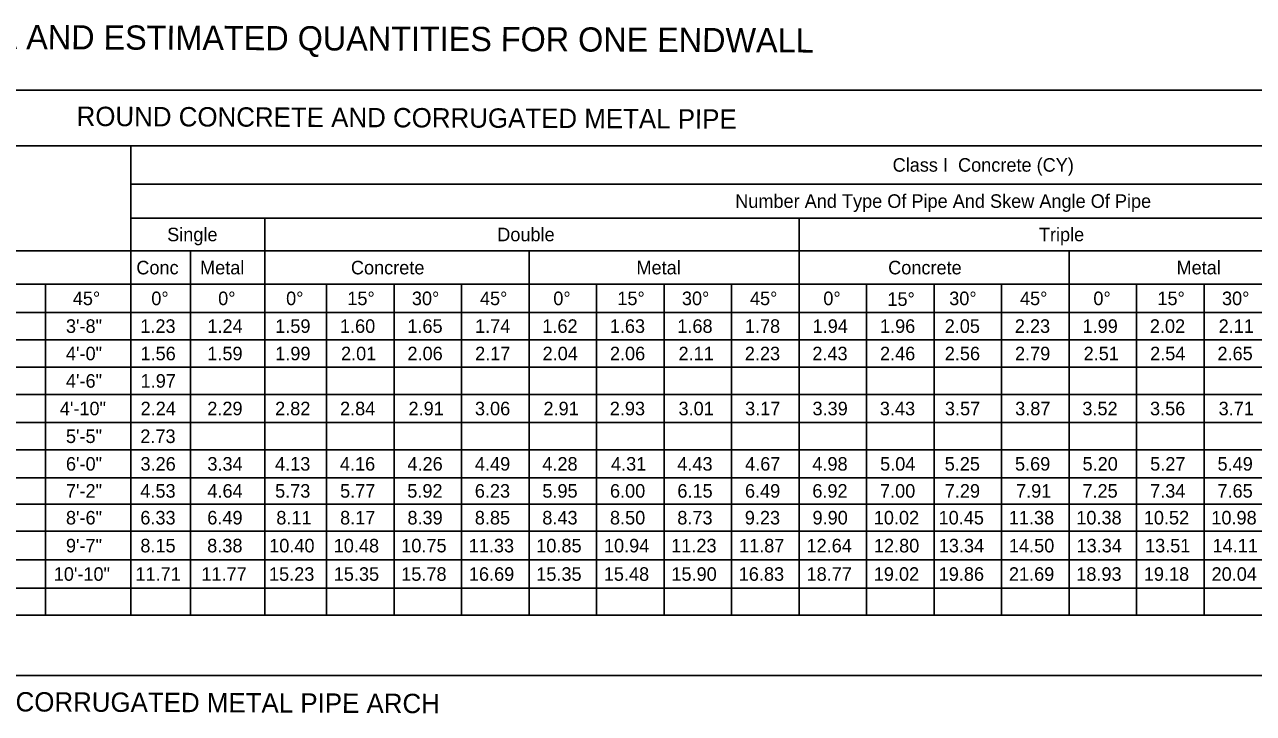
# Model space of a CAD drawing. Extents: x 10029 to 10796, y 10063 to 10519.
# Drawn here: x 10299.4 to 10616.8, y 10341.1 to 10518.9 of the extents above; entities that cross this region are included whole.
import ezdxf

# ---------------------------------------------------------------- set-up
doc = ezdxf.new("R2010")
doc.units = 0
doc.layers.add('Default', color=7, linetype='Continuous')
doc.layers.add('TextStructures', color=7, linetype='Continuous')

msp = doc.modelspace()

# ---------------------------------------------------------------- linework, layer by layer
at = {"layer": 'Default'}
for p, q in [((10028.97, 10502.01), (10795.89, 10502.01)), ((10028.97, 10487.65), (10795.89, 10487.65)), ((10326.86, 10366.47), (10326.86, 10487.65)), ((10326.86, 10477.72), (10783.03, 10477.72)), ((10326.86, 10468.97), (10783.03, 10468.97)), ((10361.4, 10366.47), (10361.4, 10468.97)), ((10499.44, 10366.47), (10499.44, 10468.97)), ((10042.36, 10460.49), (10783.03, 10460.49)), ((10342.27, 10366.47), (10342.27, 10460.49)), ((10429.69, 10366.47), (10429.69, 10460.49)), ((10569.19, 10366.47), (10569.19, 10460.49)), ((10244.78, 10451.88), (10783.03, 10451.88)), ((10304.74, 10366.47), (10304.74, 10451.88)), ((10377.37, 10366.47), (10377.37, 10451.88)), ((10394.81, 10366.47), (10394.81, 10451.88)), ((10412.25, 10366.47), (10412.25, 10451.88)), ((10447.13, 10366.47), (10447.13, 10451.88)), ((10464.57, 10366.47), (10464.57, 10451.88)), ((10482, 10366.47), (10482, 10451.88)), ((10516.88, 10366.47), (10516.88, 10451.88)), ((10534.32, 10366.47), (10534.32, 10451.88)), ((10551.76, 10366.47), (10551.76, 10451.88)), ((10586.63, 10366.47), (10586.63, 10451.88)), ((10604.07, 10366.47), (10604.07, 10451.88)), ((10028.97, 10444.58), (10795.89, 10444.58)), ((10028.97, 10437.55), (10795.89, 10437.55)), ((10028.97, 10430.43), (10795.89, 10430.43)), ((10028.97, 10423.41), (10795.89, 10423.41)), ((10028.97, 10416.18), (10795.89, 10416.18)), ((10028.97, 10409.08), (10795.89, 10409.08)), ((10028.97, 10401.92), (10795.89, 10401.92)), ((10028.97, 10395.12), (10795.89, 10395.12)), ((10028.97, 10388.08), (10795.89, 10388.08)), ((10028.97, 10380.7), (10795.89, 10380.7)), ((10028.97, 10373.4), (10795.89, 10373.4)), ((10028.97, 10366.47), (10795.89, 10366.47)), ((10039.72, 10350.86), (10681.45, 10350.86))]:
    msp.add_line(p, q, dxfattribs=at)

# ---------------------------------------------------------------- texts
at = {"layer": 'TextStructures'}
for s, height, rotation, p in [('DATA AND ESTIMATED QUANTITIES FOR ONE ENDWALL', 6.25, 359.7555, (10275.18, 10512.68)), ('ROUND CONCRETE AND CORRUGATED METAL PIPE', 5, 359.7555, (10312.81, 10492.75)), ('3\'-8"', 3.5, 0, (10310.06, 10439.32)), ('1.23', 3.5, 0, (10329.27, 10439.32)), ('1.24', 3.5, 0, (10346.6, 10439.32)), ('1.59', 3.5, 0, (10364.12, 10439.32)), ('1.60', 3.5, 0, (10380.84, 10439.32)), ('1.65', 3.5, 0, (10398.25, 10439.32)), ('1.74', 3.5, 0, (10415.74, 10439.32)), ('1.62', 3.5, 0, (10433.11, 10439.32)), ('1.63', 3.5, 0, (10450.54, 10439.32)), ('1.68', 3.5, 0, (10467.99, 10439.32)), ('1.78', 3.5, 0, (10485.43, 10439.32)), ('1.94', 3.5, 0, (10502.93, 10439.32)), ('1.96', 3.5, 0, (10520.34, 10439.32)), ('2.05', 3.5, 0, (10537.05, 10439.32)), ('2.23', 3.5, 0, (10555.17, 10439.32)), ('1.99', 3.5, 0, (10572.65, 10439.32)), ('2.02', 3.5, 0, (10590.05, 10439.32)), ('2.11', 3.5, 0, (10607.81, 10439.32)), ('4\'-0"', 3.5, 0, (10310.06, 10432.24)), ('1.56', 3.5, 0, (10329.31, 10432.24)), ('1.59', 3.5, 0, (10346.57, 10432.24)), ('1.99', 3.5, 0, (10364.12, 10432.24)), ('2.01', 3.5, 0, (10381.11, 10432.24)), ('2.06', 3.5, 0, (10398.27, 10432.24)), ('2.17', 3.5, 0, (10415.75, 10432.24)), ('2.04', 3.5, 0, (10433.18, 10432.24)), ('2.06', 3.5, 0, (10450.58, 10432.24)), ('2.11', 3.5, 0, (10468.3, 10432.24)), ('2.23', 3.5, 0, (10485.42, 10432.24)), ('2.43', 3.5, 0, (10502.86, 10432.24)), ('2.46', 3.5, 0, (10520.34, 10432.24)), ('2.56', 3.5, 0, (10537.07, 10432.24)), ('2.79', 3.5, 0, (10555.21, 10432.24)), ('2.51', 3.5, 0, (10572.93, 10432.24)), ('2.54', 3.5, 0, (10590.12, 10432.24)), ('2.65', 3.5, 0, (10607.51, 10432.24)), ('4\'-6"', 3.5, 0, (10310.06, 10425.17)), ('1.97', 3.5, 0, (10329.35, 10425.17)), ('4\'-10"', 3.5, 0, (10308.48, 10418.04)), ('2.24', 3.5, 0, (10329.34, 10418.04)), ('2.29', 3.5, 0, (10346.57, 10418.04)), ('2.82', 3.5, 0, (10364.09, 10418.04)), ('2.84', 3.5, 0, (10380.86, 10418.04)), ('2.91', 3.5, 0, (10398.55, 10418.04)), ('3.06', 3.5, 0, (10415.71, 10418.04)), ('2.91', 3.5, 0, (10433.42, 10418.04)), ('2.93', 3.5, 0, (10450.54, 10418.04)), ('3.01', 3.5, 0, (10468.3, 10418.04)), ('3.17', 3.5, 0, (10485.5, 10418.04)), ('3.39', 3.5, 0, (10502.9, 10418.04)), ('3.43', 3.5, 0, (10520.3, 10418.04)), ('3.57', 3.5, 0, (10537.11, 10418.04)), ('3.87', 3.5, 0, (10555.26, 10418.04)), ('3.52', 3.5, 0, (10572.61, 10418.04)), ('3.56', 3.5, 0, (10590.09, 10418.04)), ('3.71', 3.5, 0, (10607.81, 10418.04)), ('5\'-5"', 3.5, 0, (10310.06, 10410.88)), ('2.73', 3.5, 0, (10329.27, 10410.88)), ('6\'-0"', 3.5, 0, (10310.06, 10403.75)), ('3.26', 3.5, 0, (10329.31, 10403.75)), ('3.34', 3.5, 0, (10346.6, 10403.75)), ('4.13', 3.5, 0, (10364.08, 10403.75)), ('4.16', 3.5, 0, (10380.83, 10403.75)), ('4.26', 3.5, 0, (10398.27, 10403.75)), ('4.49', 3.5, 0, (10415.71, 10403.75)), ('4.28', 3.5, 0, (10433.12, 10403.75)), ('4.31', 3.5, 0, (10450.86, 10403.75)), ('4.43', 3.5, 0, (10467.98, 10403.75)), ('4.67', 3.5, 0, (10485.5, 10403.75)), ('4.98', 3.5, 0, (10502.87, 10403.75)), ('5.04', 3.5, 0, (10520.37, 10403.75)), ('5.25', 3.5, 0, (10537.05, 10403.75)), ('5.69', 3.5, 0, (10555.21, 10403.75)), ('5.20', 3.5, 0, (10572.66, 10403.75)), ('5.27', 3.5, 0, (10590.13, 10403.75)), ('5.49', 3.5, 0, (10607.53, 10403.75)), ('7\'-2"', 3.5, 0, (10310.06, 10396.77)), ('4.53', 3.5, 0, (10329.27, 10396.77)), ('4.64', 3.5, 0, (10346.6, 10396.77)), ('5.73', 3.5, 0, (10364.08, 10396.77)), ('5.77', 3.5, 0, (10380.87, 10396.77)), ('5.92', 3.5, 0, (10398.23, 10396.77)), ('6.23', 3.5, 0, (10415.67, 10396.77)), ('5.95', 3.5, 0, (10433.12, 10396.77)), ('6.00', 3.5, 0, (10450.59, 10396.77)), ('6.15', 3.5, 0, (10468, 10396.77)), ('6.49', 3.5, 0, (10485.46, 10396.77)), ('6.92', 3.5, 0, (10502.86, 10396.77)), ('7.00', 3.5, 0, (10520.34, 10396.77)), ('7.29', 3.5, 0, (10537.07, 10396.77)), ('7.91', 3.5, 0, (10555.49, 10396.77)), ('7.25', 3.5, 0, (10572.63, 10396.77)), ('7.34', 3.5, 0, (10590.12, 10396.77)), ('7.65', 3.5, 0, (10607.51, 10396.77)), ('8\'-6"', 3.5, 0, (10310.06, 10389.85)), ('6.33', 3.5, 0, (10329.27, 10389.85)), ('6.49', 3.5, 0, (10346.57, 10389.85)), ('8.11', 3.5, 0, (10364.4, 10389.85)), ('8.17', 3.5, 0, (10380.87, 10389.85)), ('8.39', 3.5, 0, (10398.27, 10389.85)), ('8.85', 3.5, 0, (10415.68, 10389.85)), ('8.50', 3.5, 0, (10450.59, 10389.85)), ('8.73', 3.5, 0, (10467.98, 10389.85)), ('9.23', 3.5, 0, (10485.42, 10389.85)), ('9.90', 3.5, 0, (10502.91, 10389.85)), ('10.02', 3.5, 0, (10518.73, 10389.85)), ('10.45', 3.5, 0, (10535.48, 10389.85)), ('11.38', 3.5, 0, (10553.61, 10389.85)), ('10.38', 3.5, 0, (10571.05, 10389.85)), ('10.52', 3.5, 0, (10588.48, 10389.85)), ('10.98', 3.5, 0, (10605.93, 10389.85)), ('9\'-7"', 3.5, 0, (10310.06, 10382.64)), ('8.15', 3.5, 0, (10329.28, 10382.64)), ('8.38', 3.5, 0, (10346.55, 10382.64)), ('10.40', 3.5, 0, (10362.56, 10382.64)), ('10.48', 3.5, 0, (10379.23, 10382.64)), ('10.75', 3.5, 0, (10396.67, 10382.64)), ('11.33', 3.5, 0, (10414.1, 10382.64)), ('10.85', 3.5, 0, (10431.55, 10382.64)), ('10.94', 3.5, 0, (10449.04, 10382.64)), ('11.23', 3.5, 0, (10466.41, 10382.64)), ('11.87', 3.5, 0, (10483.93, 10382.64)), ('12.64', 3.5, 0, (10501.36, 10382.64)), ('12.80', 3.5, 0, (10518.77, 10382.64)), ('13.34', 3.5, 0, (10535.53, 10382.64)), ('14.50', 3.5, 0, (10553.65, 10382.64)), ('13.34', 3.5, 0, (10571.11, 10382.64)), ('13.51', 3.5, 0, (10588.8, 10382.64)), ('14.11', 3.5, 0, (10606.23, 10382.64)), ('10\'-10"', 3.5, 0, (10306.91, 10375.3)), ('11.71', 3.5, 0, (10328.01, 10375.3)), ('11.77', 3.5, 0, (10345.04, 10375.3)), ('15.23', 3.5, 0, (10362.51, 10375.3)), ('15.35', 3.5, 0, (10379.24, 10375.3)), ('15.78', 3.5, 0, (10396.67, 10375.3)), ('18.77', 3.5, 0, (10501.37, 10375.3)), ('19.02', 3.5, 0, (10518.73, 10375.3)), ('19.86', 3.5, 0, (10535.5, 10375.3)), ('21.69', 3.5, 0, (10553.64, 10375.3)), ('CORRUGATED METAL PIPE ARCH', 5, 359.7555, (10297.04, 10341.57))]:
    msp.add_text(s, height=height, rotation=rotation, dxfattribs=at).set_placement(p)
for s, p in [('Class I  Concrete (CY)', (10523.6, 10480.94)), ('Number And Type Of Pipe And Skew Angle Of Pipe', (10482.94, 10471.6)), ('Single', (10336.2, 10462.98)), ('Double', (10421.47, 10462.98)), ('Triple', (10561.38, 10462.98)), ('Conc', (10328.24, 10454.43)), ('Metal', (10344.7, 10454.43)), ('Concrete', (10383.67, 10454.43)), ('Metal', (10457.43, 10454.43)), ('Concrete', (10522.45, 10454.43)), ('Metal', (10596.94, 10454.43)), ('45°', (10311.83, 10446.48)), ('0°', (10332.11, 10446.48)), ('0°', (10349.38, 10446.48)), ('0°', (10366.93, 10446.48)), ('15°', (10382.74, 10446.48)), ('30°', (10399.42, 10446.48)), ('45°', (10417, 10446.48)), ('0°', (10435.95, 10446.48)), ('15°', (10452.49, 10446.48)), ('30°', (10469.17, 10446.48)), ('45°', (10486.75, 10446.48)), ('0°', (10505.7, 10446.48)), ('15°', (10522.25, 10446.3)), ('30°', (10538.22, 10446.48)), ('45°', (10556.5, 10446.48)), ('0°', (10575.46, 10446.48)), ('15°', (10592, 10446.48)), ('30°', (10608.68, 10446.48)), ('8.43', (10433.11, 10389.85)), ('16.69', (10414.14, 10375.3)), ('15.35', (10431.55, 10375.3)), ('15.48', (10448.99, 10375.3)), ('15.90', (10466.46, 10375.3)), ('16.83', (10483.85, 10375.3)), ('18.93', (10571.04, 10375.3)), ('19.18', (10588.49, 10375.3)), ('20.04', (10605.99, 10375.3))]:
    msp.add_text(s, height=3.5, dxfattribs=at).set_placement(p)

doc.saveas('drawing.dxf')
